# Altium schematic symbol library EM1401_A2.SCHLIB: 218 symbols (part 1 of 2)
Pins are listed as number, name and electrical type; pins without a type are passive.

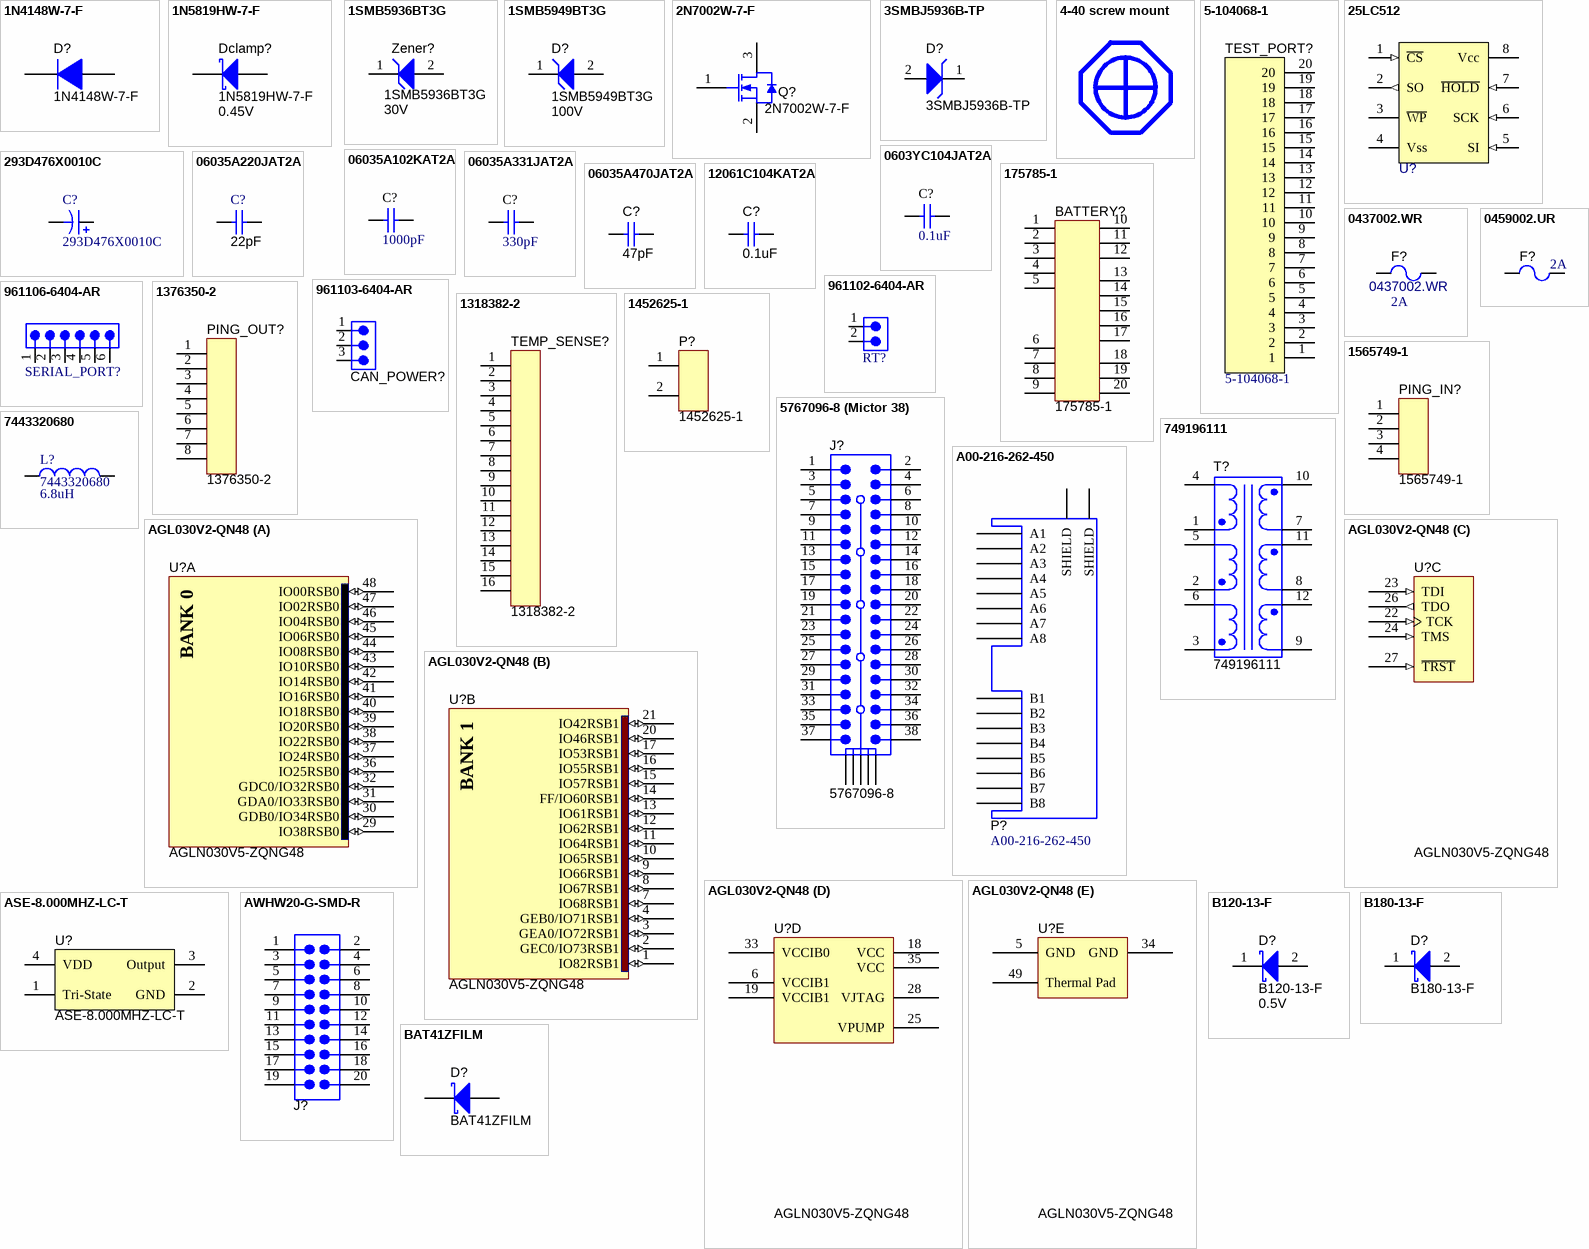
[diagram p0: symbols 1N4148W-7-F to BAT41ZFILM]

## 1N4148W-7-F
designator D?
Diode, Ultrafast, 100V, 0.15A, SOD-123; Manufacturer: Diodes Inc.; U/M: EA; Vf_V: 1.25; Io_A: 0.15; Vr_V: 100; TJmax_C: 150; Value: 1.25V
signal-integrity model Diode
simulation model 1N4148W
footprint SOD-123
pins: 1 K, 2 A

## 1N5819HW-7-F
designator Dclamp?  value 0.45V
Diode, Schottky, 40V, 1A, SOD-123; Manufacturer: Diodes Inc.; Vf_V: 0.45; Io_A: 1; Vr_V: 40; TJMax_C: 125; U/M: EA
signal-integrity model Diode
simulation model DI_1N5819HW
footprint SOD-123
pins: 1 K, 2 A

## 1SMB5936BT3G
designator Zener?  value 30V
Diode, Zener, 30V, 550mW, SMB; Manufacturer: ON Semiconductor; U/M: EA; Power_W: 0.55; Vz: 30; Value1: 0.55W; RJA_CperW: 226
signal-integrity model Diode
simulation model 1smb5936bt3
footprint SMB
pins: 1 K, 2 A

## 1SMB5949BT3G
designator D?  value 100V
Diode, Zener, 100V, 550mW, SMB; Manufacturer: ON Semiconductor; U/M: EA; Power_W: 0.55; Vz: 100; Value1: 0.55W; RJA_CperW: 226
signal-integrity model Diode
footprint SMB
pins: 1 K, 2 A

## 2N7002W-7-F
designator Q?
MOSFET N-CH 60V 115MA SOT323; Manufacturer: Vishay-Siliconix; ChType: N; VdsMax_V: 60; Value1: 1.8 ohm; Rdson45_Ohm: 1.8; Value2: 0.4 nC; QgTyp_nC: 0.4; Vgs_V: 20; IdsMax_A: 0.24
footprint SOT-323 (SC-70-3 and SOT-323 footrpint)
pins: 1 G, 2 S, 3 D

## 3SMBJ5936B-TP
designator D?
DIODE ZENER 3W 30V SMB; Manufacturer: Micro Commercial Components; SymbolCreator: cwiosc
footprint SMB (Molded Diode, 2-Leads, Body 5.4x3.6mm, IPC Medium Density, based on OnSemi component dimensions)
pins: 1 A, 2 K

## 4-40 screw mount
designator MNT?, comment Used in BOM report  (value not drawn)
4-40 screw for mounting hardware; SymbolVersion: use current date i.e. 2008-05-20; SymbolCreator: Use LDAP id
footprint 4-40 screw (Hole and Pad for 4-40 screw mount)

## 5-104068-1
designator TEST_PORT?
20Pin AMP Connector VERT HEADER; Manufacturer: AMP Incorporated
footprint 5-104068-1 (TYCO HEADER ASSEMBLY, VERTICAL, DOUBLE ROW, W/SIDE &END LATCHES)
pins: 1, 2, 3, 4, 5, 6, 7, 8, 9, 10, 11, 12, 13, 14, 15, 16, 17, 18, 19, 20

## 25LC512
designator U?, comment 25LC512T-I/SN  (value not drawn)
IC EEPROM 512KBIT 20MHZ; Manufacturer: Micorchip Technology; SymbolVersion: use current date i.e. 2008-05-20; SymbolCreator: Use LDAP id
footprint M08A_N (SOIC, 8-Leads, Body 4.9x3.9mm, Pitch 1.27mm, IPC Medium Density)
footprint M08A_L (SOIC, 8-Leads, Body 4.9x3.9mm, Pitch 1.27mm, IPC High Density)
pins: 1 ~{CS} (in), 2 SO (out), 3 ~{WP}, 4 Vss (power), 5 SI (in), 6 SCK (in), 7 ~{HOLD} (in), 8 Vcc (power)

## 293D476X0010C
designator C?
CAP TANT 47UF 10V 20% SMD; Manufacturer: Vishay/Sprague; CompType: Capacitor Tant.
footprint 6032-28 (Medium Density IPC based on Vishay Sprague 293D datasheet.)
pins: 1 +, 2 -

## 0603YC104JAT2A
designator C?  value 0.1uF  (hidden comment: 0603YC104JAT2A)
Ceramic, X7R, 16V, 5%; Manufacturer: AVX; Cap_Case: 0603; ESR_Ohm: 0.039; Polarized: N; TaMax_C: 125; TaMin_C: -55; Tolerance_%: 5; VDC_V: 16; Cap_F: 100.0E-9; CompType: Capacitor; Value1: 0.039 Ohm
signal-integrity model Cap
simulation model Cap
footprint 0603
footprint 0603M
footprint 0603L (0603 from SM-752 data)
pins: 1, 2

## 06035A102KAT2A
designator C?  value 1000pF  (hidden comment: 06035A102KAT2A)
Ceramic, C0G/NP0, 50V, 10%; Manufacturer: AVX; Cap_Case: 0603; ESR_Ohm: 0.048; Polarized: N; TaMax_C: 125; TaMin_C: -55; Tolerance_%: 10; VDC_V: 50; Cap_F: 1.0E-9; CompType: Capacitor; Value1: 0.048 Ohm
signal-integrity model Cap
simulation model Cap
footprint 0603
footprint 0603M
footprint 0603L (0603 from SM-752 data)
footprint 0603_HV
pins: 1, 2

## 06035A220JAT2A
designator C?  ValueDisplayed: 22pF  (hidden comment: 06035A220JAT2A)
CAP, CERM, 22pF, 50V, +/-5%, C0G/NP0, 0603; Manufacturer: AVX; Cap_Case: 0603; ESR_Ohm: 0.259; Polarized: N; TaMax_C: 125; TaMin_C: -55; Tolerance_%: 5; VDC_V: 50; Cap_F: 22.0E-12; CompType: Capacitor; Value1: 0.259 ohm
signal-integrity model Cap
simulation model Cap
footprint 0603
footprint 0603M
footprint 0603L
footprint 0603_HV
pins: 1, 2

## 06035A331JAT2A
designator C?  value 330pF  (hidden comment: 06035A331JAT2A)
Ceramic, C0G/NP0, 50V, 5%; Manufacturer: AVX; Cap_Case: 0603; ESR_Ohm: 0.071; Polarized: N; TaMax_C: 125; TaMin_C: -55; Tolerance_%: 5; VDC_V: 50; Cap_F: 330.0E-12; CompType: Capacitor; Value1: 0.071 Ohm
signal-integrity model Cap
simulation model Cap
footprint 0603
footprint 0603M
footprint 0603L (0603 from SM-752 data)
footprint 0603_HV
pins: 1, 2

## 06035A470JAT2A
designator C?  value 47pF  (hidden comment: 06035A470JAT2A)
Ceramic, C0G/NP0, 50V, 5%; Manufacturer: AVX; Cap_Case: 0603; ESR_Ohm: 0.174; Polarized: N; TaMax_C: 125; TaMin_C: -55; Tolerance_%: 5; VDC_V: 50; Cap_F: 47.0E-12; CompType: Capacitor; Value1: 0.174 Ohm
signal-integrity model Cap
simulation model Cap
footprint 0603
footprint 0603M
footprint 0603L (0603 from SM-752 data)
footprint 0603_HV
pins: 1, 2

## 12061C104KAT2A
designator C?  value 0.1uF  (hidden comment: 12061C104KAT2A)
Ceramic, X7R, 100V, 10%; Manufacturer: AVX; Cap_Case: 1206; ESR_Ohm: 0.037; Polarized: N; TaMax_C: 125; TaMin_C: -55; Tolerance_%: 10; VDC_V: 100; Cap_F: 100.0E-9; CompType: Capacitor; Value1: 0.037 Ohm
signal-integrity model Cap
simulation model Cap
footprint 1206
footprint 1206M
footprint 1206L
pins: 1, 2

## 175785-1
designator BATTERY?
.070 SERIES MULTI-LOCK I/O CONN. 20Pos. PCB 90 Horiz; Manufacturer: Tyco; CompType: Connector
footprint 175785 (.070 SERIES MULTI-LOCK I/O CONN. 20Pos. PCB 90)
pins: 1, 2, 3, 4, 5, 6, 7, 8, 9, 10, 11, 12, 13, 14, 15, 16, 17, 18, 19, 20

## 0437002.WR
designator F?  value 2A
FUSE 2A 63V  FAST ACTING; Manufacturer: LittleFuse Inc; SymbolVersion: use current date i.e. 2008-05-20; SymbolCreator: Use LDAP id
footprint 1206M (1206 from SM-752 data)
pins: 1, 2

## 0459002.UR
designator F?  value 2A  (hidden comment: 0459002.UR)
FUSE 2A 125V  FAST ACTING; Manufacturer: LittleFuse Inc; SymbolVersion: use current date i.e. 2008-05-20; SymbolCreator: Use LDAP id
pins: 1, 2

## 961102-6404-AR
designator RT?  (value not drawn)
CONN 1X2 HEADER 100mil pitch; Manufacturer: 3M; CompType: Connector; I max: 2A
footprint 1X2 100MIL PITCH (CONN HEADER VERT SGL 2POS)
pins: 1, 2

## 961103-6404-AR
designator CAN_POWER?  (value not drawn)
CONN 1X3 HEADER 100mil pitch; Manufacturer: 3M; CompType: Connector; I max: 2A
footprint 1X3 100MIL PITCH (CONN HEADER VERT SGL 3POS)
pins: 1, 2, 3

## 961106-6404-AR
designator SERIAL_PORT?  (value not drawn)
CONN 1X6 HEADER 100mil pitch; Manufacturer: 3M; CompType: Connector; I max: 2A
footprint 1X6 100MIL PITCH (CONN HEADER VERT SGL 6POS)
pins: 1, 2, 3, 4, 5, 6

## 1318382-2
designator TEMP_SENSE?
Tyco 025 Series Multi-Lock Connector 16 position
footprint 1318382-2 (Tyco 025 Series Multi-Lock Connector 16 position)
pins: 1, 2, 3, 4, 5, 6, 7, 8, 9, 10, 11, 12, 13, 14, 15, 16

## 1376350-2
designator PING_OUT?
Tyco 025 Series Multi-Lock Connector 8 position
footprint 1376350-2 (Tyco 025 Series Multi-Lock Connector 8 position)
pins: 1, 2, 3, 4, 5, 6, 7, 8

## 1452625-1
designator P?
Tyco .64 Series GET Connector 2 position
footprint 1452625-1 (Tyco Automotive, Unsealed PCB Horizontal HDR, 2x1)
pins: 1, 2

## 1565749-1
designator PING_IN?
Tyco 025 Series Multi-Lock Connector 4 position
footprint 1565749-1 (Tyco 025 Series Multi-Lock Connector 4 position)
pins: 1, 2, 3, 4

## 5767096-8 (Mictor 38)
designator J?, comment 5767096-8
Mictor Receptacle, SMD 25mil, 19x2, Gold plated, 236 mil above insulator; Manufacturer: Tyco Electronics; U/M: EA
pins: 1, 2, 3, 4, 5, 6, 7, 8, 9, 10, 11, 12, 13, 14, 15, 16, 17, 18, 19, 20, 21, 22, 23, 24, 25, 26, 27, 28, 29, 30, 31, 32, 33, 34, 35, 36, 37, 38, 39, 40, 41, 42, 43

## 749196111
designator T?
Wurth 749196111 flyback transformer; Manufacturer: Wurth Elektronik; SymbolVersion: use current date i.e. 2008-05-20; SymbolCreator: Use LDAP id; CompType: Used in some BOM reports.  Useful for finding later.
footprint 749196111 (flyback transformer)
pins: 1, 2, 3, 4, 5, 6, 7, 8, 9, 10, 11, 12

## 7443320680
designator L?  Ind_H: 6.8uH
Wurth 6.8uH Power Inductor; Manufacturer: Wurth Elektronik; DCR_Ohm: 8.98; Value1: 13A
footprint Wurth 7443320680 (Wurth Inductor 6.8uH - Power Choke WE-HCC)
pins: 1, 2

## A00-216-262-450
designator P?
RJ45 2X1 8 Position Jack; Manufacturer: EDAC; CompType: Connector
footprint A00-216-262-450 (CONN RJ45 MODJACK 1X2 R/A SHIELD)
pins: 10 SHIELD "Shield", 10 SHIELD "Shield", A1, A2, A3, A4, A5, A6, A7, A8, B1, B2, B3, B4, B5, B6, B7, B8

## AGL030V2-QN48
designator U?, comment AGLN030V5-ZQNG48
IGLOO Low-Power Flash 1.2/1.5V FPGA with Flash*Freeze, 34 User IOs, 30K System Gates, 1Kbit Flash ROM, 48-Pin QFN, Commercial Grade; Manufacturer: Actel
footprint QN48_N (QFN, 48-Leads, Body 6x6 mm, Pitch 0.4mm, IPC Medium Density)
footprint QN48_L (QFN, 48-Leads, Body 6x6 mm, Pitch 0.4mm, IPC High Density)
footprint QN48_M (QFN, 48-Leads, Body 6x6 mm, Pitch 0.4mm, IPC Low Density)
3D model AGL030-QN48 (48-Pin Quad Flat No-Lead 0.4 mm Pitch (QN48))
signal-integrity model AGL030-QN48 (IGLOO)
part A pins: 29 IO38RSB0 (io), 30 GDB0/IO34RSB0 (io), 31 GDA0/IO33RSB0 (io), 32 GDC0/IO32RSB0 (io), 36 IO25RSB0 (io), 37 IO24RSB0 (io), 38 IO22RSB0 (io), 39 IO20RSB0 (io), 40 IO18RSB0 (io), 41 IO16RSB0 (io), 42 IO14RSB0 (io), 43 IO10RSB0 (io), 44 IO08RSB0 (io), 45 IO06RSB0 (io), 46 IO04RSB0 (io), 47 IO02RSB0 (io), 48 IO00RSB0 (io)
part B pins: 1 IO82RSB1 (io), 2 GEC0/IO73RSB1 (io), 3 GEA0/IO72RSB1 (io), 4 GEB0/IO71RSB1 (io), 7 IO68RSB1 (io), 8 IO67RSB1 (io), 9 IO66RSB1 (io), 10 IO65RSB1 (io), 11 IO64RSB1 (io), 12 IO62RSB1 (io), 13 IO61RSB1 (io), 14 FF/IO60RSB1 (io), 15 IO57RSB1 (io), 16 IO55RSB1 (io), 17 IO53RSB1 (io), 20 IO46RSB1 (io), 21 IO42RSB1 (io)
part C pins: 22 TCK (in), 23 TDI (in), 24 TMS (in), 26 TDO (out), 27 ~{TRST} (in)
part D pins: 6 VCCIB1 (power), 18 VCC (power), 19 VCCIB1 (power), 25 VPUMP (power), 28 VJTAG (power), 33 VCCIB0 (power), 35 VCC (power)
part E pins: 5 GND (power), 34 GND (power), 49 Thermal Pad

## ASE-8.000MHZ-LC-T
designator U?
Oscillator, 8.000MHz, 3.3V, SMD; Manufacturer: Abracon; Tolerance_%: +/-50ppm; Frequency: 8000000; Value1: 8MHz; Value2: 7mA
footprint ASE-xxxMHz-x-x-x (ASE 3.3Vdc CMOS SMD crystal oscillator)
pins: 1 Tri-State, 2 GND, 3 Output, 4 VDD

## AWHW20-G-SMD-R
designator J?  (value not drawn)
GREY CONN SHROUDED 2x10 HEADER SMT 100mil pitch; Manufacturer: Assman Electronics; CompType: Connector
footprint 2X10 Shrouded Surface Mount HDR
pins: 1, 2, 3, 4, 5, 6, 7, 8, 9, 10, 11, 12, 13, 14, 15, 16, 17, 18, 19, 20

## B120-13-F
designator D?  value 0.5V
Diode, Schottky, 20V, 1A, SMA; Manufacturer: Diodes Inc.; RJC_CperW: 20; Vf_V: 0.5; Io_A: 1; TJMax_C: 150; U/M: EA
signal-integrity model Diode
simulation model DI_B120
footprint SMA
pins: 1 K, 2 A

## B180-13-F
designator D?
Diode, Schottky, 80V, 1A, SMA; Manufacturer: Diodes Inc.; RJC_CperW: 25; Vf_V: 0.79; Io_A: 1; Vr_V: 80; TJMax_C: 150; Value: 0.79V; U/M: EA
signal-integrity model Diode
simulation model DI_B180
footprint SMA
pins: 1 K, 2 A

## BAT41ZFILM
designator D?
Diode, Schottky, 100V, 0.2A, SOD-123; Manufacturer: ST Microelectronics; Vf_V: 1; Io_A: 0.2; Vr_V: 100; TJMax_C: 150; Value: 1V; U/M: EA
signal-integrity model Diode
simulation model BAT41
footprint SOD-123
pins: 1 K, 2 A

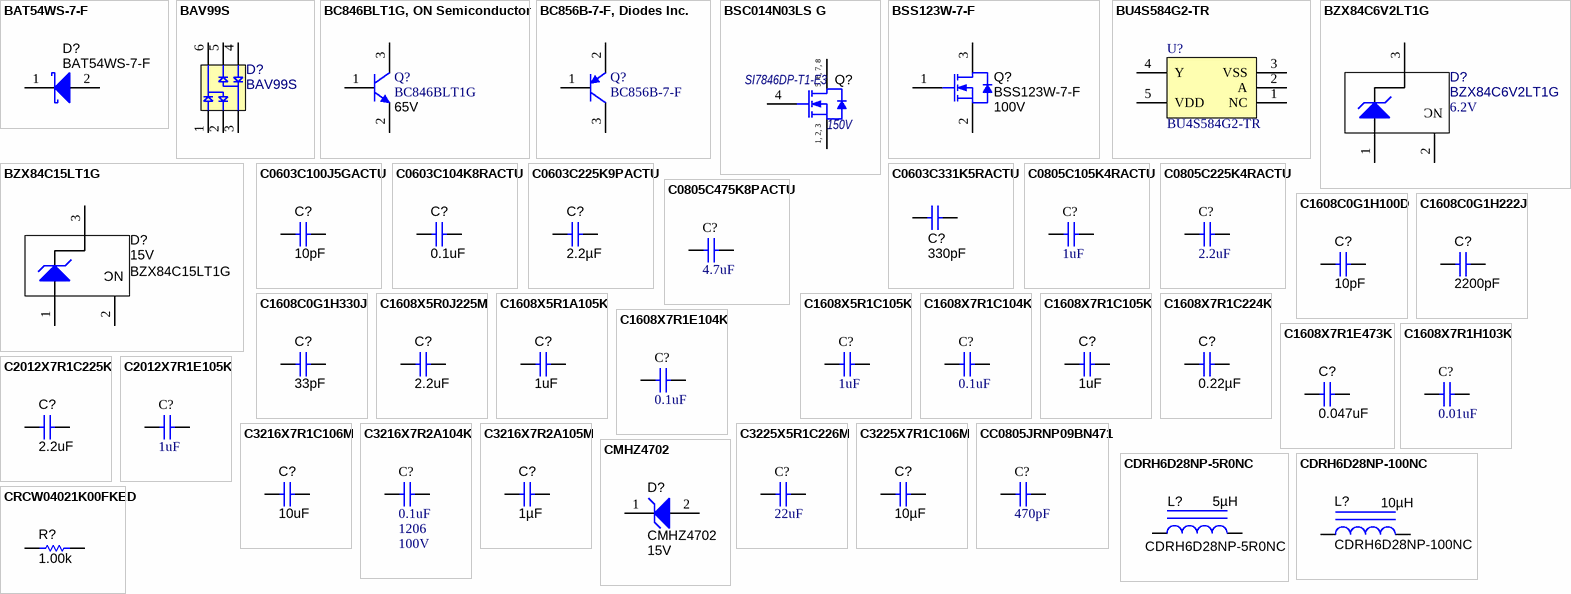
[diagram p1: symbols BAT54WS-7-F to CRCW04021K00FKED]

## BAT54WS-7-F
designator D?
Diode, Schottky, 30V, 0.2A, SOD-323; Manufacturer: Diodes Inc.; Vf_V: 0.7; Io_A: 0.2; Vr_V: 30; TJMax_C: 125; Value: 0.7V; U/M: EA
signal-integrity model Diode
simulation model DI_BAT54WS
footprint sod-323
pins: 1 K, 2 A

## BAV99S
designator D?
H-S switching diode; Manufacturer: NXP Semiconductors; SymbolVersion: use current date i.e. 2008-05-20; SymbolCreator: Use LDAP id
footprint SOT-363
pins: 1, 2, 3, 4, 5, 6

## BC846BLT1G, ON Semiconductor
designator Q?, comment BC846BLT1G  Vceo_V: 65V
Transistor, NPN, 65V, 0.1A, SOT-23; Manufacturer: ON Semiconductor; CompType: BJT; PNP: 0; NPN: 1; Vcesat1_V: 0.7; Value: 0.7V; IcRated_A: 0.1; HfeMax: 450
footprint SOT-23
footprint SOT-23M
footprint SOT-23L
simulation model bc846blt1g
pins: 1 B, 2 E, 3 C

## BC856B-7-F, Diodes Inc.
designator Q?, comment BC856B-7-F
Transistor, PNP, 65V, 0.1A, SOT-23; Manufacturer: Diodes Inc.; CompType: BJT; PNP: 1; NPN: 0; Vcesat1_V: 0.075; Value: 0.075V; IcRated_A: 0.1; HfeMax: 330
footprint SOT-23
footprint SOT-23M
footprint SOT-23L
simulation model DI_BC856B
pins: 1 B, 2 E, 3 C

## BSC014N03LS G
designator Q?, comment SI7846DP-T1-E3  value 150V
100A, 47nC, rDS(on) @ 4.5V =0.0021 Ohm; Manufacturer: Vishay/Siliconix; DesignatorOriginal: Q1-tw; A_Properties: MOSFET N-CH 150V 4A PPAK 8SOIC; Type: N-CH FET; Value1: 50mOhm; Value2: 30nC
footprint PowerPAK_SO-8 (Vishay PowerPAK SO-8, Body 5.3x6.0mm (max), Pitch 1.27mm, IPC Medium Density)
pins: 1 S, 2 S, 3 S, 4 G, 5 D, 6 D, 7 D, 8 D

## BSS123W-7-F
designator Q?  value 100V
MOSFET, N-CH, 100V, 0.17A, SOT-323; Manufacturer: Diodes Inc.; U/M: EA; ChType: N; VdsMax_V: 100; Value1: 10 ohm; Rdson45_Ohm: 10; Value2: ? nC; Vgs_V: 20; IdsMax_A: 0.17
footprint SOT-323
simulation model DI_BSS123W
pins: 1 G, 2 S, 3 D

## BU4S584G2-TR
designator U?
IC INVERTER WITH SCHMITT TRIGGER SINGLE; Manufacturer: Rohm Semiconductor; Res_Ohm: 200000; Value1: 3V-16V; Value2: 3.4mA Drive
footprint MF05A_M (SOT23, 5-Leads, Body 2.9x1.6mm, Pitch 0.95mm, Lead Span 2.8mm, IPC Low Density)
pins: 1 NC, 2 A, 3 VSS, 4 Y, 5 VDD

## BZX84C6V2LT1G
designator D?  value 6.2V
SMT Zener Diode; Manufacturer: ON Semiconductor; Power_W: 0.225; Vz: 6.2; Value1: 0.225V; RJA_CperW: 556
signal-integrity model Diode
footprint SOT-23
pins: 1 A, 2 NC, 3 K
1 alternate drawing of the same symbol

## BZX84C15LT1G
designator D?  value 15V
Diode, Zener, 15V, 225mW, SOT-23; Manufacturer: ON Semiconductor; Power_W: 0.225; Vz: 15; Value1: 0.225W; RJA_CperW: 556
signal-integrity model Diode
footprint SOT-23
pins: 1 A, 2 NC, 3 K
1 alternate drawing of the same symbol

## C0603C100J5GACTU
designator C?  value 10pF  (hidden comment: C0603C100J5GACTU)
Ceramic, C0G/NP0, 50V, 5%; Manufacturer: Kemet; Cap_Case: 0603; Polarized: N; TaMax_C: 125; TaMin_C: -55; Tolerance_%: 5; VDC_V: 50; Cap_F: 10.0E-12; CompType: Capacitor
signal-integrity model Cap
simulation model Cap
footprint 0603
footprint 0603M
footprint 0603L (0603 from SM-752 data)
footprint 0603_HV
pins: 1, 2

## C0603C104K8RACTU
designator C?  value 0.1uF  (hidden comment: C0603C104K8RACTU)
Ceramic, X7R, 10V, 10%; Manufacturer: Kemet; Cap_Case: 0603; Polarized: N; TaMax_C: 125; TaMin_C: -55; Tolerance_%: 10; Cap_F: 100.0E-9; CompType: Capacitor
signal-integrity model Cap
simulation model Cap
footprint 0603
footprint 0603M
footprint 0603L (0603 from SM-752 data)
footprint 0603_HV
pins: 1, 2

## C0603C225K9PACTU
designator C?  ValueDisplayed: 2.2µF  (hidden comment: C0603C225K9PACTU)
CAP, CERM, 2.2uF, 6.3V, +/-10%, X5R, 0603; Manufacturer: Kemet; Cap_Case: 0603; Polarized: N; TaMax_C: 85; TaMin_C: -55; Tolerance_%: 10; VDC_V: 6.3; Cap_F: 0.0000022; CompType: Capacitor; U/M: EA
signal-integrity model Cap
simulation model Cap
footprint 0603
footprint 0603M
footprint 0603L
footprint 0603_HV
pins: 1, 2

## C0603C331K5RACTU
designator C?  ValueDisplayed: 330pF  (hidden comment: C0603C331K5RACTU)
CAP, CERM, 330pF, 50V, +/-10%, X7R, 0603; Manufacturer: Kemet; Cap_Case: 0603; Polarized: N; TaMax_C: 125; TaMin_C: -55; Tolerance_%: 10; VDC_V: 50; Cap_F: 0.00000000033; CompType: Capacitor; U/M: EA
signal-integrity model Cap
simulation model Cap
footprint 0603
footprint 0603M
footprint 0603L
footprint 0603_HV
pins: 1, 2

## C0805C105K4RACTU
designator C?  value 1uF  (hidden comment: C0805C105K4RACTU)
Ceramic, X7R, 16V, 10%; Manufacturer: Kemet; Cap_Case: 0805; ESR_Ohm: 0.015; IRMS_A: 8.19; Polarized: N; TaMax_C: 125; TaMin_C: -55; Tolerance_%: 10; VDC_V: 16; Cap_F: 1.0E-6; CompType: Capacitor; Value1: 0.015 Ohm
signal-integrity model Cap
simulation model Cap
footprint 0805_HV
footprint 0805
footprint 0805M
footprint 0805L
pins: 1, 2

## C0805C225K4RACTU
designator C?  value 2.2uF  (hidden comment: C0805C225K4RACTU)
Ceramic, X7R, 16V, 10%; Manufacturer: Kemet; Cap_Case: 0805; ESR_Ohm: 0.008; IRMS_A: 15.55; Polarized: N; TaMax_C: 125; TaMin_C: -55; Tolerance_%: 10; VDC_V: 16; Cap_F: 2.2E-6; CompType: Capacitor; Value1: 0.008 Ohm
signal-integrity model Cap
simulation model Cap
footprint 0805_HV
footprint 0805
footprint 0805M
footprint 0805L
pins: 1, 2

## C0805C475K8PACTU
designator C?  value 4.7uF  (hidden comment: C0805C475K8PACTU)
Ceramic, X5R, 10V, 10%; Manufacturer: Kemet; Cap_Case: 0805; ESR_Ohm: 0.004; IRMS_A: 9.89; Polarized: N; TaMax_C: 85; TaMin_C: -55; Tolerance_%: 10; Cap_F: 4.7E-6; CompType: Capacitor; Value1: 0.004 Ohm
signal-integrity model Cap
simulation model Cap
footprint 0805_HV
footprint 0805
footprint 0805M
footprint 0805L
pins: 1, 2

## C1608C0G1H100D
designator C?  ValueDisplayed: 10pF  (hidden comment: C1608C0G1H100D)
CAP, CERM, 10pF, 50V, +/-5%, C0G/NP0, 0603; Manufacturer: TDK; Cap_Case: 0603; ESR_Ohm: 0.3492; Polarized: N; TaMax_C: 125; TaMin_C: -55; Tolerance_%: 5; VDC_V: 50; Cap_F: 0.00000000001; CompType: Capacitor; U/M: EA; Value1: 0.3492 ohm
signal-integrity model Cap
simulation model Cap
footprint 0603
footprint 0603M
footprint 0603L
footprint 0603_HV
pins: 1, 2

## C1608C0G1H222J
designator C?  value 2200pF  (hidden comment: C1608C0G1H222J)
Ceramic, C0G/NP0, 50V, 5%; Manufacturer: TDK; Cap_Case: 0603; ESR_Ohm: 0.0375; Polarized: N; TaMax_C: 125; TaMin_C: -55; Tolerance_%: 5; VDC_V: 50; Cap_F: 2.2E-9; CompType: Capacitor; Value1: 0.0375 Ohm
signal-integrity model Cap
simulation model Cap
footprint 0603
footprint 0603M
footprint 0603L (0603 from SM-752 data)
footprint 0603_HV
pins: 1, 2

## C1608C0G1H330J
designator C?  value 33pF  (hidden comment: C1608C0G1H330J)
Ceramic, C0G/NP0, 50V, 5%; Manufacturer: TDK; Cap_Case: 0603; ESR_Ohm: 0.2649; Polarized: N; TaMax_C: 125; TaMin_C: -55; Tolerance_%: 5; VDC_V: 50; Cap_F: 33.0E-12; CompType: Capacitor; Value1: 0.2649 Ohm
signal-integrity model Cap
simulation model Cap
footprint 0603
footprint 0603M
footprint 0603L
footprint 0603_HV
pins: 1, 2

## C1608X5R0J225M
designator C?  value 2.2uF  (hidden comment: C1608X5R0J225M)
Ceramic, X5R, 6.3V, 20%; Manufacturer: TDK; Cap_Case: 0603; ESR_Ohm: 0.004; Polarized: N; TaMax_C: 85; TaMin_C: -55; Tolerance_%: 20; VDC_V: 6.3; Cap_F: 2.2E-6; CompType: Capacitor; Value1: 0.004 Ohm
signal-integrity model Cap
simulation model Cap
footprint 0603
footprint 0603M
footprint 0603L (0603 from SM-752 data)
footprint 0603_HV
pins: 1, 2

## C1608X5R1A105K
designator C?  value 1uF  (hidden comment: C1608X5R1A105K)
Ceramic, X5R, 10V, 10%; Manufacturer: TDK; Cap_Case: 0603; ESR_Ohm: 0.0057; Polarized: N; TaMax_C: 85; TaMin_C: -55; Tolerance_%: 10; Cap_F: 1.0E-6; CompType: Capacitor; Value1: 0.0057 Ohm
signal-integrity model Cap
simulation model Cap
footprint 0603
footprint 0603M
footprint 0603L (0603 from SM-752 data)
footprint 0603_HV
pins: 1, 2

## C1608X5R1C105K
designator C?  value 1uF  (hidden comment: C1608X5R1C105K)
Ceramic, X5R, 16V, 10%; Manufacturer: TDK; Cap_Case: 0603; ESR_Ohm: 0.0057; Polarized: N; TaMax_C: 85; TaMin_C: -55; Tolerance_%: 10; VDC_V: 16; Cap_F: 1.0E-6; CompType: Capacitor; Value1: 0.0057 Ohm
signal-integrity model Cap
simulation model Cap
footprint 0603
footprint 0603M
footprint 0603L (0603 from SM-752 data)
pins: 1, 2

## C1608X7R1C104K
designator C?  value 0.1uF  (hidden comment: C1608X7R1C104K)
Ceramic, X7R, 16V, 10%; Manufacturer: TDK; Cap_Case: 0603; ESR_Ohm: 0.017; Polarized: N; TaMax_C: 125; TaMin_C: -55; Tolerance_%: 10; VDC_V: 16; Cap_F: 100.0E-9; CompType: Capacitor; Value1: 0.017 Ohm
signal-integrity model Cap
simulation model Cap
footprint 0603
footprint 0603M
footprint 0603L (0603 from SM-752 data)
pins: 1, 2

## C1608X7R1C105K
designator C?  value 1uF  (hidden comment: C1608X7R1C105K)
Ceramic, X7R, 16V, 10%; Manufacturer: TDK; Cap_Case: 0603; ESR_Ohm: 0.0057; Polarized: N; TaMax_C: 125; TaMin_C: -55; Tolerance_%: 10; VDC_V: 16; Cap_F: 1.0E-6; CompType: Capacitor; Value1: 0.0057 Ohm
signal-integrity model Cap
simulation model Cap
footprint 0603
footprint 0603M
footprint 0603L (0603 from SM-752 data)
footprint 0603_HV
pins: 1, 2

## C1608X7R1C224K
designator C?  ValueDisplayed: 0.22µF  (hidden comment: C1608X7R1C224K)
CAP, CERM, 0.22uF, 16V, +/-10%, X7R, 0603; Manufacturer: TDK; Cap_Case: 0603; ESR_Ohm: 0.0125; Polarized: N; TaMax_C: 125; TaMin_C: -55; Tolerance_%: 10; VDC_V: 16; Cap_F: 0.00000022; CompType: Capacitor; U/M: EA; Value1: 0.0125 ohm
signal-integrity model Cap
simulation model Cap
footprint 0603
footprint 0603M
footprint 0603L
footprint 0603_HV
pins: 1, 2

## C1608X7R1E104K
designator C?  value 0.1uF  (hidden comment: C1608X7R1E104K)
Ceramic, X7R, 25V, 10%; Manufacturer: TDK; Cap_Case: 0603; ESR_Ohm: 0.017; Polarized: N; TaMax_C: 125; TaMin_C: -55; Tolerance_%: 10; VDC_V: 25; Cap_F: 100.0E-9; CompType: Capacitor; Value1: 0.017 Ohm
signal-integrity model Cap
simulation model Cap
footprint 0603
footprint 0603M
footprint 0603L (0603 from SM-752 data)
pins: 1, 2

## C1608X7R1E473K
designator C?  value 0.047uF  (hidden comment: C1608X7R1E473K)
Ceramic, X7R, 25V, 10%; Manufacturer: TDK; Cap_Case: 0603; ESR_Ohm: 0.0234; Polarized: N; TaMax_C: 125; TaMin_C: -55; Tolerance_%: 10; VDC_V: 25; Cap_F: 47.0E-9; CompType: Capacitor; Value1: 0.0234 Ohm
signal-integrity model Cap
simulation model Cap
footprint 0603
footprint 0603M
footprint 0603L (0603 from SM-752 data)
footprint 0603_HV
pins: 1, 2

## C1608X7R1H103K
designator C?  value 0.01uF  (hidden comment: C1608X7R1H103K)
Ceramic, X7R, 50V, 10%; Manufacturer: TDK; Cap_Case: 0603; ESR_Ohm: 0.0539; Polarized: N; TaMax_C: 125; TaMin_C: -55; Tolerance_%: 10; VDC_V: 50; Cap_F: 10.0E-9; CompType: Capacitor; Value1: 0.0539 Ohm
signal-integrity model Cap
simulation model Cap
footprint 0603
footprint 0603M
footprint 0603L (0603 from SM-752 data)
pins: 1, 2

## C2012X7R1C225K
designator C?  value 2.2uF  (hidden comment: C2012X7R1C225K)
Ceramic, X7R, 16V, 10%; Manufacturer: TDK; Cap_Case: 0805; ESR_Ohm: 0.0049; Polarized: N; TaMax_C: 125; TaMin_C: -55; Tolerance_%: 10; VDC_V: 16; Cap_F: 2.2E-6; CompType: Capacitor; Value1: 0.0049 Ohm
signal-integrity model Cap
simulation model Cap
footprint 0805_HV
footprint 0805
footprint 0805M
footprint 0805L
pins: 1, 2

## C2012X7R1E105K
designator C?  value 1uF  (hidden comment: C2012X7R1E105K)
Ceramic, X7R, 25V, 10%; Manufacturer: TDK; Cap_Case: 0805; ESR_Ohm: 0.0075; Polarized: N; TaMax_C: 125; TaMin_C: -55; Tolerance_%: 10; VDC_V: 25; Cap_F: 1.0E-6; CompType: Capacitor; Value1: 0.0075 Ohm
signal-integrity model Cap
simulation model Cap
footprint 0805_HV
footprint 0805
footprint 0805M
footprint 0805L
pins: 1, 2

## C3216X7R1C106M
designator C?  value 10uF  (hidden comment: C3216X7R1C106M)
Ceramic, X7R, 16V, 20%; Manufacturer: TDK; Cap_Case: 1206; ESR_Ohm: 0.0046; Polarized: N; TaMax_C: 125; TaMin_C: -55; Tolerance_%: 20; VDC_V: 16; Cap_F: 10.0E-6; CompType: Capacitor; Value1: 0.0046 Ohm
signal-integrity model Cap
simulation model Cap
footprint 1206
footprint 1206M
footprint 1206L
pins: 1, 2

## C3216X7R2A104K
designator C?  value 0.1uF  PackageReference: 1206  Value2: 100V  (hidden comment: C3216X7R2A104K)
Ceramic, X7R, 100V, 10%; Manufacturer: TDK; ESR_Ohm: 0.0259; IRMS_A: 1.5; Polarized: N; TaMax_C: 125; TaMin_C: -55; Tolerance_%: 10; VDC_V: 100; Cap_F: 100.0E-9; CompType: Capacitor; Value1: 0.0259 Ohm
signal-integrity model Cap
simulation model Cap
footprint 1206
footprint 1206M
footprint 1206L
pins: 1, 2

## C3216X7R2A105M
designator C?  value 1µF  (hidden comment: C3216X7R2A105M)
CAP, CERM, 1µF, 100V, +/-20%, C Series, 1206; Manufacturer: TDK; Cap_Case: 1206; ESR_Ohm: 0.006; IRMS_A: 4.5; Polarized: N; TaMax_C: 125; TaMin_C: -55; Tolerance_%: 20; VDC_V: 100; Cap_F: 1.0E-6; CompType: Capacitor; Value1: 0.006 ohm
signal-integrity model Cap
simulation model Cap
footprint 1206
footprint 1206M
footprint 1206L
pins: 1, 2

## C3225X5R1C226M
designator C?  value 22uF  (hidden comment: C3225X5R1C226M)
Ceramic, X5R, 16V, 20%; Manufacturer: TDK; Cap_Case: 1210; ESR_Ohm: 0.002; IRMS_A: 3.5; Polarized: N; TaMax_C: 85; TaMin_C: -55; Tolerance_%: 20; VDC_V: 16; Cap_F: 22.0E-6; CompType: Capacitor; Value1: 0.002 Ohm
signal-integrity model Cap
simulation model Cap
footprint 1210
footprint 1210M
footprint 1210L
pins: 1, 2

## C3225X7R1C106M
designator C?  ValueDisplayed: 10µF  (hidden comment: C3225X7R1C106M)
CAP, CERM, 10uF, 16V, +/-20%, X7R, 1210; Manufacturer: TDK; Cap_Case: 1210; ESR_Ohm: 0.0027; IRMS_A: 3; Polarized: N; TaMax_C: 125; TaMin_C: -55; Tolerance_%: 20; VDC_V: 16; Cap_F: 10.0E-6; CompType: Capacitor; Value1: 0.0027 ohm
signal-integrity model Cap
simulation model Cap
footprint 1210
footprint 1210M
footprint 1210L
pins: 1, 2

## CC0805JRNP09BN471
designator C?  value 470pF  (hidden comment: CC0805JRNP09BN471)
Ceramic, C0G/NP0, 50V, 5%; Manufacturer: Yageo America; Cap_Case: 0805; Polarized: N; TaMax_C: 125; TaMin_C: -55; Tolerance_%: 5; VDC_V: 50; Cap_F: 470.0E-12; CompType: Capacitor
signal-integrity model Cap
simulation model Cap
footprint 0805_HV
footprint 0805
footprint 0805M
footprint 0805L
pins: 1, 2

## CDRH6D28NP-5R0NC
designator L?  ValueDisplayed: 5µH
Inductor, Shielded Drum Core, Ferrite, 5uH, 2.4A, 0.031 ohm, SMD; Manufacturer: Sumida; Ind_H: 5.0E-6; Imax_A: 2.4; Irms: 2.4A @ 30C rise; Isat: 2.4A @ 35% inductance drop; DCR_ohm: 0.031; U/M: EA
signal-integrity model Inductor
simulation model Inductor
footprint CDRH6D28
pins: 1, 2

## CDRH6D28NP-100NC
designator L?  ValueDisplayed: 10µH
Inductor, Shielded Drum Core, Ferrite, 10uH, 1.7A, 0.065 ohm, SMD; Manufacturer: Sumida; Ind_H: 10.0E-6; Imax_A: 1.7; Irms: 1.7A @ 30C rise; Isat: 1.7A @ 35% inductance drop; DCR_ohm: 0.065; U/M: EA
signal-integrity model Inductor
simulation model Inductor
footprint CDRH6D28
pins: 1, 2

## CMHZ4702
designator D?  value 15V
Diode, Zener, 15V, 500mW, SOD-123; Manufacturer: Central Semiconductor; U/M: EA; Power_W: 0.5; Vz: 15; Value1: 0.5W; RJA_CperW: 350
signal-integrity model Diode
footprint SOD-123
pins: 1 K, 2 A

## CRCW04021K00FKED
designator R?  value 1.00k  (hidden comment: CRCW04021K00FKED)
RES, 1.00k ohm, 1%, 0.063W, 0402; Manufacturer: Vishay-Dale; CompType: Resistor; Tolerance_%: 1; VDC_V: 50; Power_W: 0.063; Res_ohm: 1000; Value_Code: 1k00; TempCo_ppm/C: 100; EIA_Code: E96; U/M: EA
signal-integrity model Resistor
simulation model Resistor
footprint 0402
footprint 0402M
footprint 0402L
pins: 1, 2

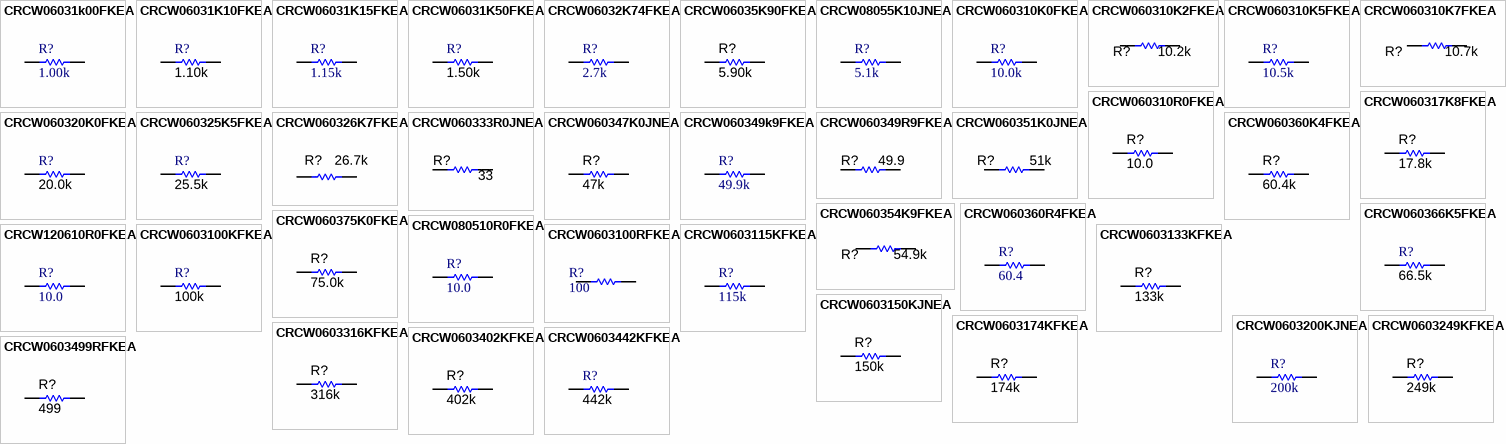
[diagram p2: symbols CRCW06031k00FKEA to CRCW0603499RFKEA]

## CRCW06031k00FKEA
designator R?  value 1.00k  (hidden comment: CRCW06031k00FKEA)
1%, 0.1W; Manufacturer: Vishay-Dale; CompType: Resistor; Tolerance_%: 1; VDC_V: 75; Power_W: 0.1; Res_Ohm: 1000; Value_Code: 1k00; EIA_Code: E96
signal-integrity model Resistor
simulation model Resistor
footprint 0603
footprint 0603M
footprint 0603L
pins: 1, 2

## CRCW06031K10FKEA
designator R?  value 1.10k  (hidden comment: CRCW06031K10FKEA)
RES, 1.10k ohm, 1%, 0.1W, 0603; Manufacturer: Vishay-Dale; CompType: Resistor; Tolerance_%: 1; VDC_V: 75; Power_W: 0.1; Res_Ohm: 1100; Value_Code: 1k10; EIA_Code: E96
signal-integrity model Resistor
simulation model Resistor
footprint 0603
footprint 0603M
footprint 0603L
footprint 0603_HV
pins: 1, 2

## CRCW06031K15FKEA
designator R?  value 1.15k  (hidden comment: CRCW06031K15FKEA)
1%, 0.1W; Manufacturer: Vishay-Dale; CompType: Resistor; Tolerance_%: 1; VDC_V: 75; Power_W: 0.1; Res_Ohm: 1150; Value_Code: 1k15; EIA_Code: E96
signal-integrity model Resistor
simulation model Resistor
footprint 0603
footprint 0603M
footprint 0603L
footprint 0603_HV
pins: 1, 2

## CRCW06031K50FKEA
designator R?  value 1.50k  (hidden comment: CRCW06031K50FKEA)
RES, 1.50k ohm, 1%, 0.1W, 0603; Manufacturer: Vishay-Dale; CompType: Resistor; Tolerance_%: 1; VDC_V: 75; Power_W: 0.1; Res_ohm: 1500; Value_Code: 1k50; TempCo_ppm/C: 100; EIA_Code: E96; U/M: EA
signal-integrity model Resistor
simulation model Resistor
footprint 0603
footprint 0603M
footprint 0603L
footprint 0603_HV
pins: 1, 2

## CRCW06032K74FKEA
designator R?, comment value 2.7k  (hidden comment: ERJ-3EKF2701V)
1%, 0.1W; Manufacturer: Vishay-Dale; CompType: Resistor; Tolerance_%: 1; VDC_V: 75; Power_W: 0.1; Res_Ohm: 2700; Value_Code: 2k7; EIA_Code: E96
signal-integrity model Resistor
simulation model Resistor
footprint 0603
footprint 0603M
footprint 0603L
footprint 0603_HV
pins: 1, 2

## CRCW06035K90FKEA
designator R?  value 5.90k  (hidden comment: CRCW06035K90FKEA)
RES, 5.90k ohm, 1%, 0.1W, 0603; Manufacturer: Vishay-Dale; CompType: Resistor; Tolerance_%: 1; VDC_V: 75; Power_W: 0.1; Res_ohm: 5900; TempCo_ppm/C: 100; Value_Code: 5k90; EIA_Code: E96; U/M: EA
signal-integrity model Resistor
simulation model Resistor
footprint 0603
footprint 0603M
footprint 0603L
footprint 0603_HV
pins: 1, 2

## CRCW08055K10JNEA
designator R?  value 5.1k  (hidden comment: CRCW08055K10JNEA)
5%, 0.125W; Manufacturer: Vishay-Dale; CompType: Resistor; Tolerance_%: 5; VDC_V: 150; Power_W: 0.125; Res_Ohm: 5100; Value_Code: 5k10; EIA_Code: E24
signal-integrity model Resistor
simulation model Resistor
footprint 0805_HV
footprint 0805
footprint 0805M
footprint 0805L
pins: 1, 2

## CRCW060310K0FKEA
designator R?  value 10.0k  (hidden comment: CRCW060310K0FKEA)
1%, 0.1W; Manufacturer: Vishay-Dale; CompType: Resistor; Tolerance_%: 1; VDC_V: 75; Power_W: 0.1; Res_Ohm: 10000; Value_Code: 10k0; EIA_Code: E96
signal-integrity model Resistor
simulation model Resistor
footprint 0603
footprint 0603M
footprint 0603L
footprint 0603_HV
pins: 1, 2

## CRCW060310K2FKEA
designator R?  value 10.2k  (hidden comment: CRCW060310K2FKEA)
RES, 10.2k ohm, 1%, 0.1W, 0603; Manufacturer: Vishay-Dale; CompType: Resistor; Tolerance_%: 1; VDC_V: 75; Power_W: 0.1; Res_Ohm: 10200; Value_Code: 10k2; EIA_Code: E96
signal-integrity model Resistor
simulation model Resistor
footprint 0603
footprint 0603M
footprint 0603L
footprint 0603_HV
pins: 1, 2

## CRCW060310K5FKEA
designator R?  value 10.5k  (hidden comment: CRCW060310K5FKEA)
1%, 0.1W; Manufacturer: Vishay-Dale; CompType: Resistor; Tolerance_%: 1; VDC_V: 75; Power_W: 0.1; Res_Ohm: 10500; Value_Code: 10k5; EIA_Code: E96
signal-integrity model Resistor
simulation model Resistor
footprint 0603
footprint 0603M
footprint 0603L
footprint 0603_HV
pins: 1, 2

## CRCW060310K7FKEA
designator R?  value 10.7k  (hidden comment: CRCW060310K7FKEA)
RES, 10.7k ohm, 1%, 0.1W, 0603; Manufacturer: Vishay-Dale; CompType: Resistor; Tolerance_%: 1; VDC_V: 75; Power_W: 0.1; Res_Ohm: 10700; Value_Code: 10k7; EIA_Code: E96
signal-integrity model Resistor
simulation model Resistor
footprint 0603
footprint 0603M
footprint 0603L
footprint 0603_HV
pins: 1, 2

## CRCW060310R0FKEA
designator R?  value 10.0  (hidden comment: CRCW060310R0FKEA)
RES, 10.0 ohm, 1%, 0.1W, 0603; Manufacturer: Vishay-Dale; CompType: Resistor; Tolerance_%: 1; VDC_V: 75; Power_W: 0.1; Res_ohm: 10; TempCo_ppm/C: 100; Value_Code: 10R0; EIA_Code: E96; U/M: EA
signal-integrity model Resistor
simulation model Resistor
footprint 0603
footprint 0603M
footprint 0603L
footprint 0603_HV
pins: 1, 2

## CRCW060317K8FKEA
designator R?  value 17.8k  (hidden comment: CRCW060317K8FKEA)
RES, 17.8k ohm, 1%, 0.1W, 0603; Manufacturer: Vishay-Dale; CompType: Resistor; Tolerance_%: 1; VDC_V: 75; Power_W: 0.1; Res_ohm: 17800; Value_Code: 17k8; EIA_Code: E96; U/M: EA
signal-integrity model Resistor
simulation model Resistor
footprint 0603
footprint 0603M
footprint 0603L
footprint 0603_HV
pins: 1, 2

## CRCW060320K0FKEA
designator R?  value 20.0k  (hidden comment: CRCW060320K0FKEA)
RES, 20.0k ohm, 1%, 0.1W, 0603; Manufacturer: Vishay-Dale; CompType: Resistor; Tolerance_%: 1; VDC_V: 75; Power_W: 0.1; Res_ohm: 20000; Value_Code: 20k0; TempCo_ppm/C: 100; EIA_Code: E96; U/M: EA
signal-integrity model Resistor
simulation model Resistor
footprint 0603
footprint 0603M
footprint 0603L
footprint 0603_HV
pins: 1, 2

## CRCW060325K5FKEA
designator R?  value 25.5k  (hidden comment: CRCW060325K5FKEA)
RES, 25.5k ohm, 1%, 0.1W, 0603; Manufacturer: Vishay-Dale; CompType: Resistor; Tolerance_%: 1; VDC_V: 75; Power_W: 0.1; Res_Ohm: 25500; Value_Code: 25k5; EIA_Code: E96
signal-integrity model Resistor
simulation model Resistor
footprint 0603
footprint 0603M
footprint 0603L
footprint 0603_HV
pins: 1, 2

## CRCW060326K7FKEA
designator R?  value 26.7k  (hidden comment: CRCW060326K7FKEA)
RES, 26.7k ohm, 1%, 0.1W, 0603; Manufacturer: Vishay-Dale; CompType: Resistor; Tolerance_%: 1; VDC_V: 75; Power_W: 0.1; Res_ohm: 26700; TempCo_ppm/C: 100; Value_Code: 26k7; EIA_Code: E96; U/M: EA
signal-integrity model Resistor
simulation model Resistor
footprint 0603
footprint 0603M
footprint 0603L
footprint 0603_HV
pins: 1, 2

## CRCW060333R0JNEA
designator R?  value 33  (hidden comment: CRCW060333R0JNEA)
RES, 33 ohm, 5%, 0.1W, 0603; Manufacturer: Vishay-Dale; CompType: Resistor; Value_Code: 33R0; Tolerance_%: 5; Power_W: 0.1; VDC_V: 75; TempCo: 200 ppm/C; EIA_Code: E24; U/M: EA
signal-integrity model Resistor
simulation model Resistor
footprint 0603
footprint 0603M
footprint 0603L
footprint 0603_HV
pins: 1, 2

## CRCW060347K0JNEA
designator R?  value 47k  (hidden comment: CRCW060347K0JNEA)
RES, 47k ohm, 5%, 0.1W, 0603; Manufacturer: Vishay-Dale; CompType: Resistor; Tolerance_%: 5; VDC_V: 75; Power_W: 0.1; Res_Ohm: 47000; Value_Code: 47k0; EIA_Code: E24
signal-integrity model Resistor
simulation model Resistor
footprint 0603
footprint 0603M
footprint 0603L
footprint 0603_HV
pins: 1, 2

## CRCW060349k9FKEA
designator R?  value 49.9k  (hidden comment: CRCW060349k9FKEA)
1%, 0.1W; Manufacturer: Vishay-Dale; CompType: Resistor; Tolerance_%: 1; VDC_V: 75; Power_W: 0.1; Res_Ohm: 49900; Value_Code: 49k9; EIA_Code: E96
signal-integrity model Resistor
simulation model Resistor
footprint 0603
footprint 0603M
footprint 0603L
pins: 1, 2

## CRCW060349R9FKEA
designator R?  value 49.9  (hidden comment: CRCW060349R9FKEA)
RES, 49.9 ohm, 1%, 0.1W, 0603; Manufacturer: Vishay-Dale; CompType: Resistor; Tolerance_%: 1; VDC_V: 75; Power_W: 0.1; Value_Code: 49R9; EIA_Code: E96
signal-integrity model Resistor
simulation model Resistor
footprint 0603
footprint 0603M
footprint 0603L
footprint 0603_HV
pins: 1, 2

## CRCW060351K0JNEA
designator R?  value 51k  (hidden comment: CRCW060351K0JNEA)
RES, 51k ohm, 5%, 0.1W, 0603; Manufacturer: Vishay-Dale; CompType: Resistor; Tolerance_%: 5; VDC_V: 75; Power_W: 0.1; Res_Ohm: 51000; Value_Code: 51k0; EIA_Code: E24
signal-integrity model Resistor
simulation model Resistor
footprint 0603
footprint 0603M
footprint 0603L
footprint 0603_HV
pins: 1, 2

## CRCW060354K9FKEA
designator R?  value 54.9k  (hidden comment: CRCW060354K9FKEA)
RES, 54.9k ohm, 1%, 0.1W, 0603; Manufacturer: Vishay-Dale; CompType: Resistor; Tolerance_%: 1; VDC_V: 75; Power_W: 0.1; Res_ohm: 54900; Value_Code: 54k9; EIA_Code: E96; U/M: EA
signal-integrity model Resistor
simulation model Resistor
footprint 0603
footprint 0603M
footprint 0603L
footprint 0603_HV
pins: 1, 2

## CRCW060360K4FKEA
designator R?  value 60.4k  (hidden comment: CRCW060360K4FKEA)
RES, 60.4k ohm, 1%, 0.1W, 0603; Manufacturer: Vishay-Dale; CompType: Resistor; Tolerance_%: 1; VDC_V: 75; Power_W: 0.1; Res_ohm: 60400; TempCo_ppm/C: 100; Value_Code: 60k4; EIA_Code: E96; U/M: EA
signal-integrity model Resistor
simulation model Resistor
footprint 0603
footprint 0603M
footprint 0603L
footprint 0603_HV
pins: 1, 2

## CRCW060360R4FKEA
designator R?  value 60.4  (hidden comment: CRCW060360R4FKEA)
1%, 0.1W; Manufacturer: Vishay-Dale; CompType: Resistor; Tolerance_%: 1; VDC_V: 75; Power_W: 0.1; Value_Code: 60R4; EIA_Code: E96
signal-integrity model Resistor
simulation model Resistor
footprint 0603
footprint 0603M
footprint 0603L
footprint 0603_HV
pins: 1, 2

## CRCW060366K5FKEA
designator R?  value 66.5k  (hidden comment: CRCW060366K5FKEA)
RES, 66.5k ohm, 1%, 0.1W, 0603; Manufacturer: Vishay-Dale; CompType: Resistor; Tolerance_%: 1; VDC_V: 75; Power_W: 0.1; Res_Ohm: 66500; Value_Code: 66k5; EIA_Code: E96
signal-integrity model Resistor
simulation model Resistor
footprint 0603
footprint 0603M
footprint 0603L
footprint 0603_HV
pins: 1, 2

## CRCW060375K0FKEA
designator R?  value 75.0k  (hidden comment: CRCW060375K0FKEA)
RES, 75.0k ohm, 1%, 0.1W, 0603; Manufacturer: Vishay-Dale; CompType: Resistor; Tolerance_%: 1; VDC_V: 75; Power_W: 0.1; Res_ohm: 75000; TempCo_ppm/C: 100; Value_Code: 75k0; EIA_Code: E96; U/M: EA
signal-integrity model Resistor
simulation model Resistor
footprint 0603
footprint 0603M
footprint 0603L
footprint 0603_HV
pins: 1, 2

## CRCW080510R0FKEA
designator R?  value 10.0  (hidden comment: CRCW080510R0FKEA)
1%, 0.125W; Manufacturer: Vishay-Dale; CompType: Resistor; Tolerance_%: 1; VDC_V: 150; Power_W: 0.125; Res_Ohm: 10; Value_Code: 10R0; EIA_Code: E96
signal-integrity model Resistor
simulation model Resistor
footprint 0805_HV
footprint 0805
footprint 0805M
footprint 0805L
pins: 1, 2

## CRCW120610R0FKEA
designator R?  value 10.0  (hidden comment: CRCW120610R0FKEA)
1%, 0.25W; Manufacturer: Vishay-Dale; CompType: Resistor; Tolerance_%: 1; VDC_V: 200; Power_W: 0.25; Res_Ohm: 10; Value_Code: 10R0; EIA_Code: E96
signal-integrity model Resistor
simulation model Resistor
footprint 1206
footprint 1206M
footprint 1206L
pins: 1, 2

## CRCW0603100KFKEA
designator R?  value 100k  (hidden comment: CRCW0603100KFKEA)
RES, 100k ohm, 1%, 0.1W, 0603; Manufacturer: Vishay-Dale; CompType: Resistor; Tolerance_%: 1; VDC_V: 75; Power_W: 0.1; Res_ohm: 100000; TempCo_ppm/C: 100; EIA_Code: E96; U/M: EA
signal-integrity model Resistor
simulation model Resistor
footprint 0603
footprint 0603M
footprint 0603L
footprint 0603_HV
pins: 1, 2

## CRCW0603100RFKEA
designator R?  value 100  (hidden comment: CRCW0603100RFKEA)
1%, 0.1W; Manufacturer: Vishay-Dale; CompType: Resistor; Tolerance_%: 1; VDC_V: 75; Power_W: 0.1; Value_Code: 100R; EIA_Code: E96
signal-integrity model Resistor
simulation model Resistor
footprint 0603
footprint 0603M
footprint 0603L
footprint 0603_HV
pins: 1, 2

## CRCW0603115KFKEA
designator R?  value 115k  (hidden comment: CRCW0603115KFKEA)
1%, 0.1W; Manufacturer: Vishay-Dale; CompType: Resistor; Tolerance_%: 1; VDC_V: 75; Power_W: 0.1; Res_Ohm: 115000; EIA_Code: E96
signal-integrity model Resistor
simulation model Resistor
footprint 0603
footprint 0603M
footprint 0603L
footprint 0603_HV
pins: 1, 2

## CRCW0603133KFKEA
designator R?  value 133k  (hidden comment: CRCW0603133KFKEA)
RES, 133k ohm, 1%, 0.1W, 0603; Manufacturer: Vishay-Dale; CompType: Resistor; Tolerance_%: 1; VDC_V: 75; Power_W: 0.1; Res_ohm: 133000; TempCo_ppm/C: 100; EIA_Code: E96; U/M: EA
signal-integrity model Resistor
simulation model Resistor
footprint 0603
footprint 0603M
footprint 0603L
footprint 0603_HV
pins: 1, 2

## CRCW0603150KJNEA
designator R?  value 150k  (hidden comment: CRCW0603150KJNEA)
RES, 150k ohm, 5%, 0.1W, 0603; Manufacturer: Vishay-Dale; CompType: Resistor; Tolerance_%: 5; VDC_V: 75; Power_W: 0.1; Res_ohm: 150000; TempCo_ppm/C: 200; EIA_Code: E24; U/M: EA
signal-integrity model Resistor
simulation model Resistor
footprint 0603
footprint 0603M
footprint 0603L
footprint 0603_HV
pins: 1, 2

## CRCW0603174KFKEA
designator R?  value 174k  (hidden comment: CRCW0603174KFKEA)
RES, 174k ohm, 1%, 0.1W, 0603; Manufacturer: Vishay-Dale; CompType: Resistor; Res_ohm: 174000; Tolerance_%: 1; Power_W: 0.1; VDC_V: 75; TempCo: 100 ppm/C; EIA_Code: E96; U/M: EA
signal-integrity model Resistor
simulation model Resistor
footprint 0603
footprint 0603M
footprint 0603L
footprint 0603_HV
pins: 1, 2

## CRCW0603200KJNEA
designator R?  value 200k  (hidden comment: CRCW0603200KJNEA)
5%, 0.1W; Manufacturer: Vishay-Dale; CompType: Resistor; Tolerance_%: 5; VDC_V: 75; Power_W: 0.1; Res_Ohm: 200000; EIA_Code: E24
signal-integrity model Resistor
simulation model Resistor
footprint 0603
footprint 0603M
footprint 0603L
footprint 0603_HV
pins: 1, 2

## CRCW0603249KFKEA
designator R?  value 249k  (hidden comment: CRCW0603249KFKEA)
RES, 249k ohm, 1%, 0.1W, 0603; Manufacturer: Vishay-Dale; CompType: Resistor; Tolerance_%: 1; VDC_V: 75; Power_W: 0.1; Res_ohm: 249000; TempCo_ppm/C: 100; EIA_Code: E96; U/M: EA
signal-integrity model Resistor
simulation model Resistor
footprint 0603
footprint 0603M
footprint 0603L
footprint 0603_HV
pins: 1, 2

## CRCW0603316KFKEA
designator R?  value 316k  (hidden comment: CRCW0603316KFKEA)
RES, 316k ohm, 1%, 0.1W, 0603; Manufacturer: Vishay-Dale; CompType: Resistor; Tolerance_%: 1; VDC_V: 75; Power_W: 0.1; Res_Ohm: 316000; EIA_Code: E96
signal-integrity model Resistor
simulation model Resistor
footprint 0603
footprint 0603M
footprint 0603L
footprint 0603_HV
pins: 1, 2

## CRCW0603402KFKEA
designator R?  value 402k  (hidden comment: CRCW0603402KFKEA)
RES, 402k ohm, 1%, 0.1W, 0603; Manufacturer: Vishay-Dale; CompType: Resistor; Tolerance_%: 1; VDC_V: 75; Power_W: 0.1; Res_ohm: 402000; TempCo_ppm/C: 100; EIA_Code: E96; U/M: EA
signal-integrity model Resistor
simulation model Resistor
footprint 0603
footprint 0603M
footprint 0603L
footprint 0603_HV
pins: 1, 2

## CRCW0603442KFKEA
designator R?  value 442k  (hidden comment: CRCW0603442KFKEA)
RES, 442k ohm, 1%, 0.1W, 0603; Manufacturer: Vishay-Dale; CompType: Resistor; Tolerance_%: 1; VDC_V: 75; Power_W: 0.1; Res_ohm: 442000; TempCo_ppm/C: 100; EIA_Code: E96; U/M: EA
signal-integrity model Resistor
simulation model Resistor
footprint 0603
footprint 0603M
footprint 0603L
footprint 0603_HV
pins: 1, 2

## CRCW0603499RFKEA
designator R?  value 499  (hidden comment: CRCW0603499RFKEA)
RES, 499 ohm, 1%, 0.1W, 0603; Manufacturer: Vishay-Dale; CompType: Resistor; Tolerance_%: 1; VDC_V: 75; Power_W: 0.1; Value_Code: 499R; EIA_Code: E96
signal-integrity model Resistor
simulation model Resistor
footprint 0603
footprint 0603M
footprint 0603L
footprint 0603_HV
pins: 1, 2

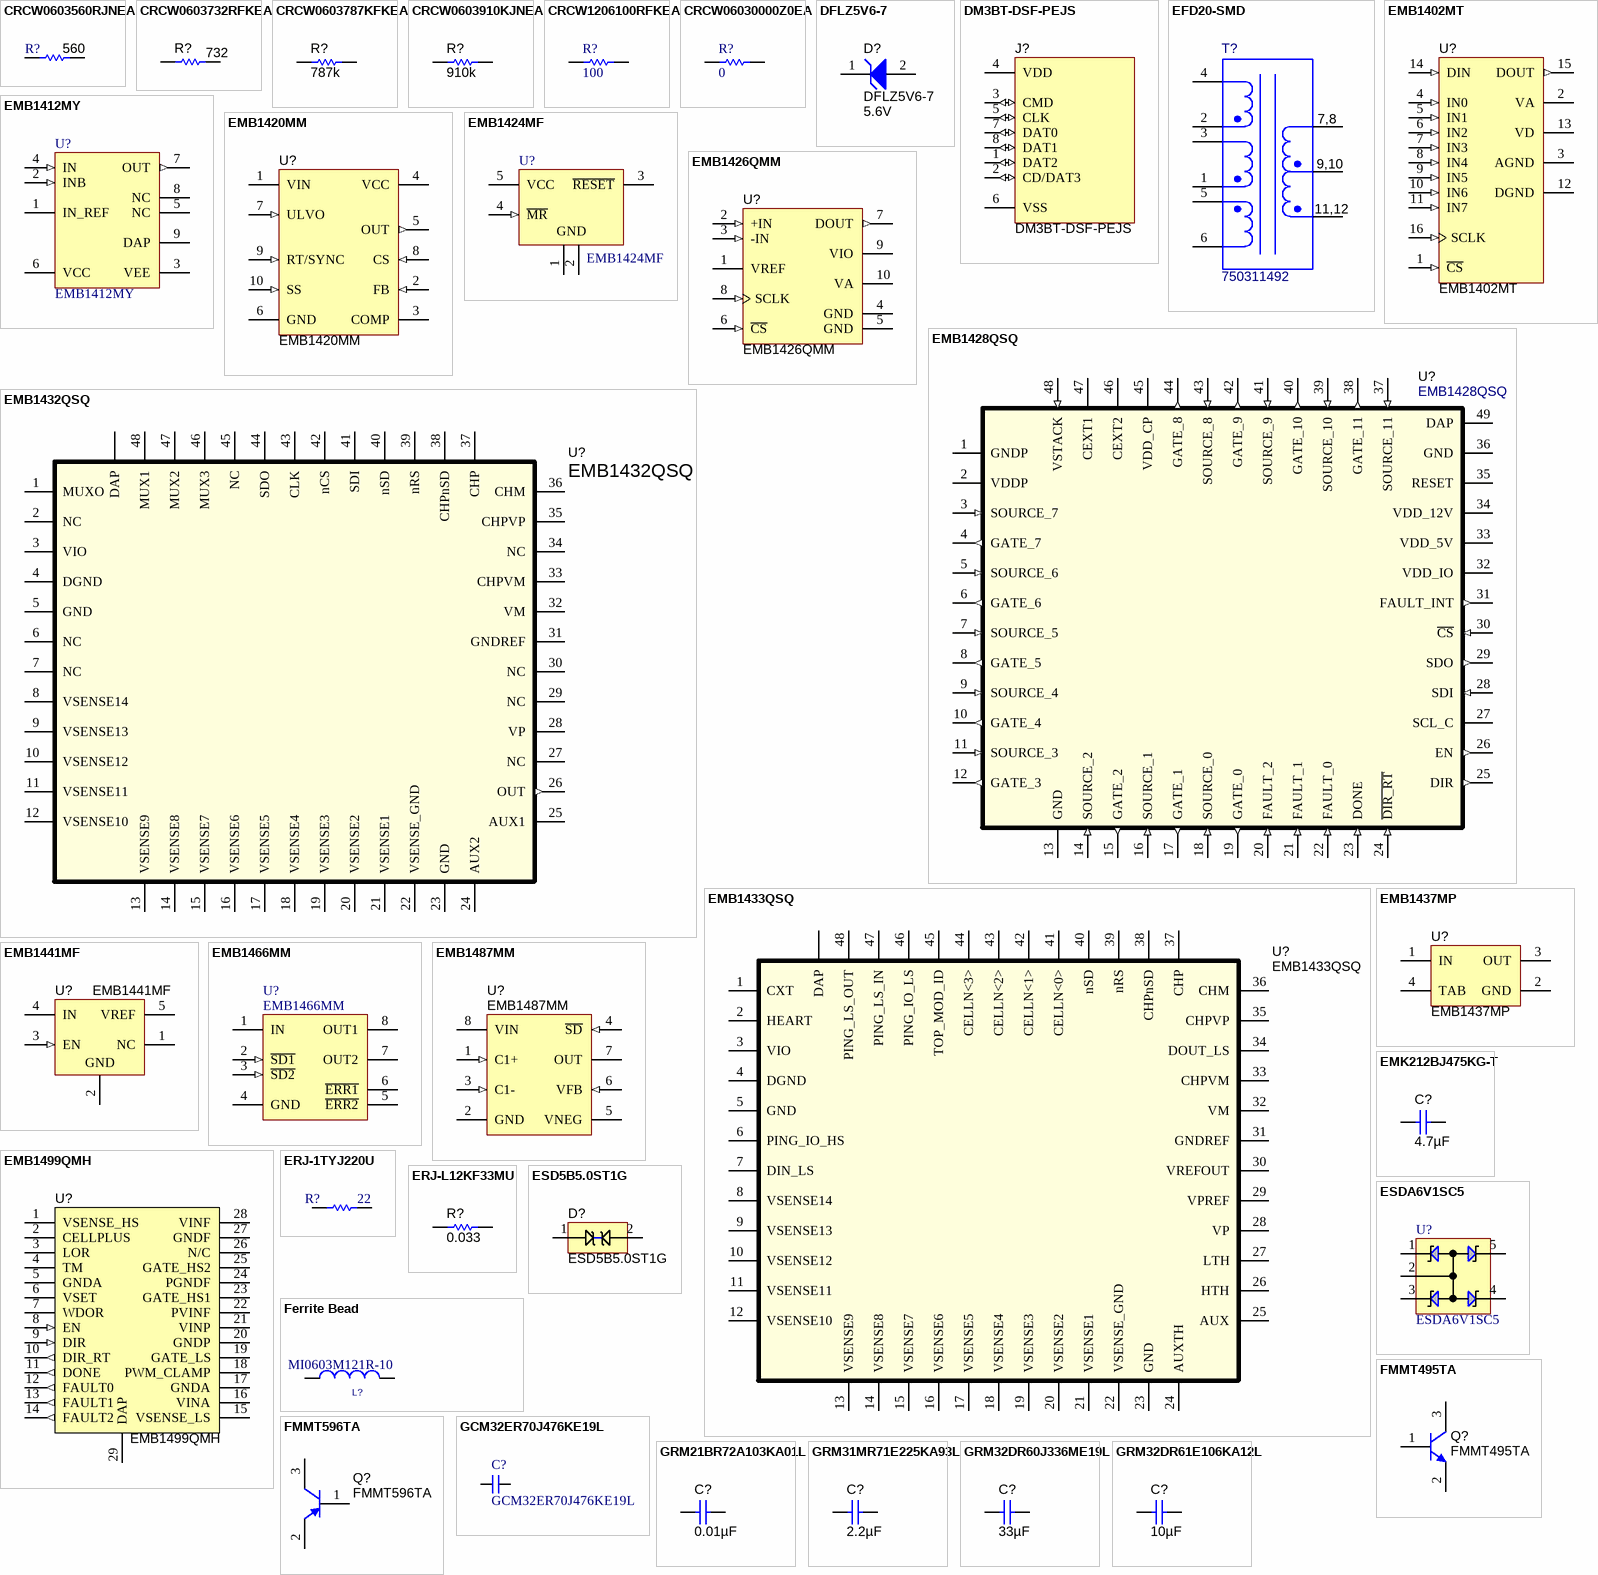
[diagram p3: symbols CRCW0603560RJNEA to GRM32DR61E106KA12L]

## CRCW0603560RJNEA
designator R?  value 560  (hidden comment: CRCW0603560RJNEA)
RES, 560 ohm, 5%, 0.1W, 0603; Manufacturer: Vishay-Dale; CompType: Resistor; Tolerance_%: 5; VDC_V: 75; Power_W: 0.1; Value_Code: 560R; EIA_Code: E24
signal-integrity model Resistor
simulation model Resistor
footprint 0603
footprint 0603M
footprint 0603L
footprint 0603_HV
pins: 1, 2

## CRCW0603732RFKEA
designator R?  value 732  (hidden comment: CRCW0603732RFKEA)
RES, 732 ohm, 1%, 0.1W, 0603; Manufacturer: Vishay-Dale; CompType: Resistor; Tolerance_%: 1; VDC_V: 75; Power_W: 0.1; Value_Code: 732R; EIA_Code: E96; U/M: EA
signal-integrity model Resistor
simulation model Resistor
footprint 0603
footprint 0603M
footprint 0603L
footprint 0603_HV
pins: 1, 2

## CRCW0603787KFKEA
designator R?  value 787k  (hidden comment: CRCW0603787KFKEA)
RES, 787k ohm, 1%, 0.1W, 0603; Manufacturer: Vishay-Dale; CompType: Resistor; Tolerance_%: 1; VDC_V: 75; Power_W: 0.1; Res_ohm: 787000; TempCo_ppm/C: 100; EIA_Code: E96; U/M: EA
signal-integrity model Resistor
simulation model Resistor
footprint 0603
footprint 0603M
footprint 0603L
footprint 0603_HV
pins: 1, 2

## CRCW0603910KJNEA
designator R?  value 910k  (hidden comment: CRCW0603910KJNEA)
RES, 910k ohm, 5%, 0.1W, 0603; Manufacturer: Vishay-Dale; CompType: Resistor; Tolerance_%: 5; VDC_V: 75; Power_W: 0.1; Res_ohm: 910000; TempCo_ppm/C: 200; EIA_Code: E24; U/M: EA
signal-integrity model Resistor
simulation model Resistor
footprint 0603
footprint 0603M
footprint 0603L
footprint 0603_HV
pins: 1, 2

## CRCW1206100RFKEA
designator R?  value 100  (hidden comment: CRCW1206100RFKEA)
1%, 0.25W; Manufacturer: Vishay-Dale; CompType: Resistor; Tolerance_%: 1; VDC_V: 200; Power_W: 0.25; Value_Code: 100R; EIA_Code: E96
signal-integrity model Resistor
simulation model Resistor
footprint 1206
footprint 1206M
footprint 1206L
pins: 1, 2

## CRCW06030000Z0EA
designator R?  value 0  (hidden comment: CRCW06030000Z0EA)
5%, 0.1W; Manufacturer: Vishay-Dale; CompType: Resistor; Tolerance_%: 5; VDC_V: 75; Power_W: 0.1; Value_Code: 0000; EIA_Code: E24
signal-integrity model Resistor
simulation model Resistor
footprint 0603
footprint 0603M
footprint 0603L
pins: 1, 2

## DFLZ5V6-7
designator D?  value 5.6V
Diode, Zener, 5.6V, 1W, PowerDI123; Manufacturer: Diodes Inc.; Power_W: 1; U/M: EA; Vz: 5.6; RJA_CperW: 110
signal-integrity model Diode
footprint powerDI123
pins: 1 K, 2 A

## DM3BT-DSF-PEJS
designator J?
CONN MICRO SD R/A PUSH-PUSH SMD; Manufacturer: Hirose; SymbolVersion: use current date i.e. 2008-05-20; SymbolCreator: Use LDAP id; CompType: Card Connector
footprint DM3BT-DSF-PEJS (Hirose DM3 series microSD card connector)
pins: 1 DAT2 (io), 2 CD/DAT3 (io), 3 CMD (io), 4 VDD (power), 5 CLK (io), 6 VSS (power), 7 DAT0 (io), 8 DAT1 (io)

## EFD20-SMD
designator T?, comment 750311492
Forward Transformer; Manufacturer: Wurth Elektronik; SymbolVersion: use current date i.e. 2008-05-20; SymbolCreator: Use LDAP id
footprint WE EFD20-SMD Transformer (Tigon Forward Transformer)
pins: 1, 2, 3, 4, 5, 6, 7, 8, 9, 10, 11, 12

## EMB1402MT
designator U?
8-Channel, 500 kSPS to 1 MSPS, 12-Bit A/D Converter; Manufacturer: National Semiconductor; CompType: ADC IC; PowerWise: Y
footprint MTC16_N (TSOP, 16-Leads, Body 5x4.4mm, Pitch 0.65mm, IPC Medium Density)
footprint MTC16_L (TSOP, 16-Leads, Body 5x4.4mm, Pitch 0.65mm, IPC High Density)
footprint MTC16_M (TSOP, 16-Leads, Body 5x4.4mm, Pitch 0.65mm, IPC Low Density)
pins: 1 ~{CS} (in), 2 VA (power), 3 AGND (power), 4 IN0 (in), 5 IN1 (in), 6 IN2 (in), 7 IN3 (in), 8 IN4 (in), 9 IN5 (in), 10 IN6 (in), 11 IN7 (in), 12 DGND (power), 13 VD (power), 14 DIN (in), 15 DOUT (out), 16 SCLK (in)

## EMB1412MY
designator U?
Dual 5A Compound Gate Driver; Manufacturer: National Semiconductor; CompType: Switcher; PowerWise: N
footprint MUY08A_N (TSOP, 8-Leads, Body 3x3mm, Pitch 0.65mm, Exposed Pad, IPC Medium Density)
footprint MUY08A_L (TSOP, 8-Leads, Body 3x3mm, Pitch 0.65mm, Exposed Pad, IPC High Density)
footprint MUY08A_M (TSOP, 8-Leads, Body 3x3mm, Pitch 0.65mm, Exposed Pad, IPC Low Density)
pins: 1 IN_REF (power), 2 INB (in), 3 VEE (power), 4 IN (in), 5 NC, 6 VCC (power), 7 OUT (out), 8 NC, 9 DAP (power)

## EMB1420MM
designator U?
100V Current Mode PWM Controller; Manufacturer: National Semiconductor; CompType: Switcher
footprint MUB10A_N (TSSOP, 10-Leads, Body 3x3mm, Pitch 0.5mm, IPC Medium Density)
footprint MUB10A_L (TSSOP, 10-Leads, Body 3x3mm, Pitch 0.5mm, IPC High Density)
footprint MUB10A_M (TSSOP, 10-Leads, Body 3x3mm, Pitch 0.5mm, IPC Low Density)
pins: 1 VIN (power), 2 FB (in), 3 COMP, 4 VCC (power), 5 OUT (out), 6 GND (power), 7 ULVO (in), 8 CS (in), 9 RT/SYNC (in), 10 SS (in)

## EMB1424MF
designator U?
5-Pin Microprocessor Reset Circuits; Manufacturer: National Semiconductor; CompType: MiscPower; PowerWise: N
footprint MF05A_N (SOT23, 5-Leads, Body 2.9x1.6mm, Pitch 0.95mm, Lead Span 2.8mm, IPC Medium Density)
footprint MF05A_L (SOT23, 5-Leads, Body 2.9x1.6mm, Pitch 0.95mm, Lead Span 2.8mm, IPC High Density)
footprint MF05A_M (SOT23, 5-Leads, Body 2.9x1.6mm, Pitch 0.95mm, Lead Span 2.8mm, IPC Low Density)
pins: 1 GND (power), 2 GND (power), 3 ~{RESET} (oc), 4 ~{MR} (in), 5 VCC (power)

## EMB1426QMM
designator U?
14-Bit, 50 kSPS to 250 kSPS, Differential Input, Micro Power A/D Converter; Manufacturer: National Semiconductor; CompType: ADC IC; PowerWise: Y
footprint MUB10A_N (TSSOP, 10-Leads, Body 3x3mm, Pitch 0.5mm, IPC Medium Density)
footprint MUB10A_L (TSSOP, 10-Leads, Body 3x3mm, Pitch 0.5mm, IPC High Density)
footprint MUB10A_M (TSSOP, 10-Leads, Body 3x3mm, Pitch 0.5mm, IPC Low Density)
pins: 1 VREF (power), 2 +IN (in), 3 -IN (in), 4 GND (power), 5 GND (power), 6 ~{CS} (in), 7 DOUT (out), 8 SCLK (in), 9 VIO (power), 10 VA (power)

## EMB1428QSQ
designator U?
12 channel Gate Controller; Manufacturer: National Semiconductor
footprint sqa48a (QFN, 48-Leads, Body 7x7mm, Pitch 0.5mm, NSC Recommended)
pins: 1 GNDP, 2 VDDP (power), 3 SOURCE_7 (in), 4 GATE_7 (out), 5 SOURCE_6 (in), 6 GATE_6 (out), 7 SOURCE_5 (in), 8 GATE_5 (out), 9 SOURCE_4 (in), 10 GATE_4 (out), 11 SOURCE_3 (in), 12 GATE_3 (out), 13 GND (power), 14 SOURCE_2 (in), 15 GATE_2 (out), 16 SOURCE_1 (in), 17 GATE_1 (out), 18 SOURCE_0 (in), 19 GATE_0 (out), 20 FAULT_2 (in), 21 FAULT_1 (in), 22 FAULT_0 (in), 23 DONE (in), 24 ~{DIR_RT} (in), 25 DIR (out), 26 EN (out), 27 SCL_C, 28 SDI (in), 29 SDO (out), 30 ~{CS} (in), 31 FAULT_INT (out), 32 VDD_IO (power), 33 VDD_5V (power), 34 VDD_12V (power), 35 RESET, 36 GND (power), 37 SOURCE_11 (in), 38 GATE_11 (out), 39 SOURCE_10 (in), 40 GATE_10 (out), 41 SOURCE_9 (in), 42 GATE_9 (out), 43 SOURCE_8 (in), 44 GATE_8 (out), 45 VDD_CP (power), 46 CEXT2, 47 CEXT1, 48 VSTACK (in), 49 DAP

## EMB1432QSQ
designator U?
14 channel AFE; Manufacturer: National Semiconductor; CompType: Used in BOM report; SymbolCreator: cwiosc
footprint SQA48B (QFN, 48-Leads, Body 7x7mm, Pitch 0.5mm, NSC Recommended)
pins: 1 MUXO, 2 NC, 3 VIO, 4 DGND, 5 GND, 6 NC, 7 NC, 8 VSENSE14, 9 VSENSE13, 10 VSENSE12, 11 VSENSE11, 12 VSENSE10, 13 VSENSE9, 14 VSENSE8, 15 VSENSE7, 16 VSENSE6, 17 VSENSE5, 18 VSENSE4, 19 VSENSE3, 20 VSENSE2, 21 VSENSE1, 22 VSENSE_GND, 23 GND, 24 AUX2, 25 AUX1, 26 OUT (out), 27 NC, 28 VP, 29 NC, 30 NC, 31 GNDREF, 32 VM, 33 CHPVM, 34 NC, 35 CHPVP, 36 CHM, 37 CHP, 38 CHPnSD, 39 nRS, 40 nSD, 41 SDI, 42 nCS, 43 CLK, 44 SDO, 45 NC, 46 MUX3, 47 MUX2, 48 MUX1, 49 DAP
